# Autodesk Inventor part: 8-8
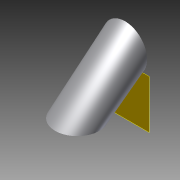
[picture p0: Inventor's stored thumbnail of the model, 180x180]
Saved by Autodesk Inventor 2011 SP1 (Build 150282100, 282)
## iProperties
Created: 2014-01
Part Number: 8-8
Document SubType Name: Modeling
Designer: Administrator
Density: 1 g/cm^3
Author: Administrator
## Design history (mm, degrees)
sketch "草图1"
  geometry: C1 r 18 at (0, 0); 1 further point
  constraints: 1 centre point, 1 coincident
  dimensions: "d0" = 36 diameter of C1
node "工作平面1"
sketch "草图2"
  geometry: L1 (0, 0)-(0, 31); C1 r 18 at (0, 31)
  constraints: 2 end point, 1 centre point, 1 coincident, 1 vertical
  dimensions: "d2" = 31 distance of L1.start L1.end; "d3" = 36 diameter of C1
feature "放样1" sketch "草图2" dims "d4" = 0, "d5" = 90 deg, "d6" = 0, "d7" = 90 deg
node "实体1"
other parameters: "d1" = 39
